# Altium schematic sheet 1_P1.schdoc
size 309 x 223 mm
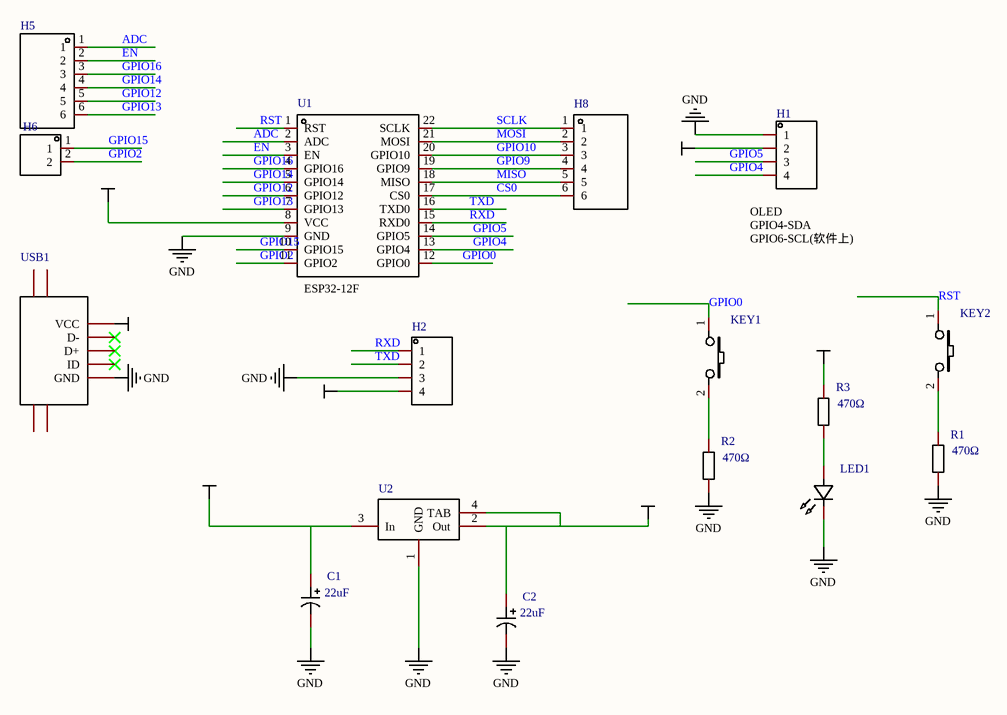
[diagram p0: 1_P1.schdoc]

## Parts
C1  value 22uF  [CAP-SMD_L3.2-W1.6]  (hidden comment: CA45-A-16V-22uF-K)
C2  value 22uF  [CAP-SMD_L3.2-W1.6]  (hidden comment: CA45-A-16V-22uF-K)
H1  B-2100S04P-A110  [HDR-TH_4P-P2.54-V-M]  (value not drawn)
H2  B-2100S04P-A110  [HDR-TH_4P-P2.54-V-M]  (value not drawn)
H5  Z-211-0611-0021-001  [HDR-TH_6P-P2.54-V_Z-211-0611-0021-001]  (value not drawn)
H6  B-2100S02P-A110  [HDR-TH_2P-P2.54-V-M-1]  (value not drawn)
H8  Z-211-0611-0021-001  [HDR-TH_6P-P2.54-V_Z-211-0611-0021-001]  (value not drawn)
KEY1  TC-3602-4.3-260G  [KEY-SMD_L6.0-W3.6-LS8.3-L]  (value not drawn)
KEY2  TC-3602-4.3-260G  [KEY-SMD_L6.0-W3.6-LS8.3-L]  (value not drawn)
LED1  19-213/GHC-ZN2Q1B8X/3T  [LED-SMD_L1.6-W0.8-RD-2]  (value not drawn)
R1  value 470Ω  [R0805]  (hidden comment: AR05DTCW1002)
R2  value 470Ω  [R0805]  (hidden comment: AR05DTCW1002)
R3  value 470Ω  [R0805]  (hidden comment: AR05DTCW1002)
U1  ESP-12F(ESP8266MOD)  [WIFIM-SMD_ESP-12F-ESP8266MOD]  (value not drawn)
U2  AMS1117-2.5  [SOT-223-4_L6.5-W3.5-P2.30-LS7.0-BR]  (value not drawn)
USB1  U-F-M5DD-Y-L  [MICRO-USB-SMD_MICRO-USB-18]  (value not drawn)

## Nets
+5V: C1.1 U2.3(In) USB1.1(VCC)
GND: C1.2 C2.2 H1.1 H2.3 LED1.2(K) R1.1 R2.1 U1.9(GND) U2.1(GND) USB1.5(GND)
VCC: C2.1 H1.2 H2.4 R3.2 U1.8(VCC) U2.2(Out) U2.4(TAB)
ADC: H5.1 U1.2(ADC)
CS0: H8.6 U1.17(CS0)
EN: H5.2 U1.3(EN)
GPIO0: KEY1.1 U1.12(GPIO0)
GPIO2: H6.2 U1.11(GPIO2)
GPIO4: H1.4 U1.13(GPIO4)
GPIO5: H1.3 U1.14(GPIO5)
GPIO9: H8.4 U1.19(GPIO9)
GPIO10: H8.3 U1.20(GPIO10)
GPIO12: H5.5 U1.6(GPIO12)
GPIO13: H5.6 U1.7(GPIO13)
GPIO14: H5.4 U1.5(GPIO14)
GPIO15: H6.1 U1.10(GPIO15)
GPIO16: H5.3 U1.4(GPIO16)
MISO: H8.5 U1.18(MISO)
MOSI: H8.2 U1.21(MOSI)
RST: KEY2.1 U1.1(RST)
RXD: H2.1 U1.15(RXD0)
SCLK: H8.1 U1.22(SCLK)
TXD: H2.2 U1.16(TXD0)
NetKEY1_2: KEY1.2 R2.2
NetKEY2_2: KEY2.2 R1.2
NetLED1_1: LED1.1(A) R3.1

Not connected (* = marked no-connect by the designer): USB1 0(SHLD) 2(D-)* 3(D+)* 4(ID)*

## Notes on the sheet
- OLED
  GPIO4-SDA
  GPIO6-SCL(软件上)
- (near U1) ESP32-12F

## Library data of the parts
C1 C2 = CA45-A-16V-22uF-K: 容值:22uF;工作温度:-55~+125;等效串联电阻:6Ω 100kHz;额定电压:16V;精度:±10%;; Manufacturer: CEC(振华新云); Add into BOM: yes; Rated Voltage: 16V; Tolerance: ±10%
H1 H2 = B-2100S04P-A110: 间距:2.54mm;总PIN位数:4;排数:1;插针结构:1x4P;行距:-;安装类型:直插;圆针/方针:-;额定电流:-;额定电压:-;配合针长度:6mm;塑高:2.54mm;端接针长度:3mm;触头材质:黄铜;触头镀层:-;工作温度范围:-40~+105;颜色:黑色;; Manufacturer: Ckmtw(灿科盟); Symbol: Header-Male-2.54_1x4; Add into BOM: yes; Pitch: 2.54mm; Pin Structure: 1x4P
H5 H8 = Z-211-0611-0021-001: 间距:2.54mm;总PIN位数:6;排数:1;插针结构:1x6P;行距:-;安装类型:直插;圆针/方针:方针;额定电流:-;额定电压:-;配合针长度:6mm;塑高:2.5mm;端接针长度:3mm;触头材质:黄铜;触头镀层:-;工作温度范围:-25~+105;颜色:黑色;; Manufacturer: Nextron(正凌); Add into BOM: yes; Pitch: 2.54mm; Pin Structure: 1x6P; Circluar Pins/Square Pins: 方针
H6 = B-2100S02P-A110: 间距:2.54mm;总PIN位数:2;排数:1;插针结构:1x2P;行距:-;安装类型:直插;圆针/方针:-;额定电流:-;额定电压:-;配合针长度:6mm;塑高:2.54mm;端接针长度:3mm;触头材质:黄铜;触头镀层:-;工作温度范围:-40~+105;颜色:黑色;; Manufacturer: Ckmtw(灿科盟); Symbol: 210S-1*2P L=11.6MMGold-plated black; Add into BOM: yes; Pitch: 2.54mm; Pin Structure: 1x2P
KEY1 KEY2 = TC-3602-4.3-260G: Manufacturer: HCTL(华灿天禄); Symbol: TC-3602-4.3-260GKK; Add into BOM: yes
LED1 = 19-213/GHC-ZN2Q1B8X/3T: Manufacturer: EVERLIGHT(亿光); Add into BOM: yes
R1-R3 = AR05DTCW1002: 温度系数:±25ppm/;阻值:10kΩ;精度:±0.5%;功率:125mW;工作温度范围:-55~+155;电阻类型:薄膜电阻;最大工作电压:100V;; Manufacturer: Viking(光颉); Add into BOM: yes; Temperature Coefficient: ±25ppm/; Tolerance: ±0.5%; Power(Watts): 125mW; Overload Voltage (Max): 100V
U1 = ESP-12F(ESP8266MOD): 屏蔽罩上的丝印是：ESP8266MOD，ESP8266EX串口WIFI; Manufacturer: Ai-Thinker(安信可); Add into BOM: yes
U2 = AMS1117-2.5: 输出类型:固定;输出极性:正;输出通道数:1;最大输入电压:15V;输出电压:2.5V;压差:1.3V@(1A);输出电流:1A;电源纹波抑制比(PRSS):72dB@(120Hz);; Manufacturer: 美国AMS; Add into BOM: yes; Output Type: 固定; Output Polarity: 正; Number of Outputs: 1; Maximum Input Voltage: 15V; Output Voltage: 2.5V
USB1 = U-F-M5DD-Y-L: 连接器类型:Micro-B;标准:USB 2.0;公母:母座;触点数量:5;端口数量:1;额定电流 - 电源:1A;; Manufacturer: 韩国韩荣; Add into BOM: yes; Gender: 母座; Number of Contacts: 5; Number of Ports: 1; Current Rating - Power (Max): 1A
